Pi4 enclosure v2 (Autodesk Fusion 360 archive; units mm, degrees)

design "Pi4 enclosure" references "40x40x10 DC Fan"
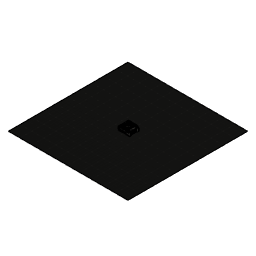
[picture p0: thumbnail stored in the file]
description: arrangementsContainer
named bodies: "Pi4_mount (1)", "LEFT", "RIGHT", "CENTRE"

design "40x40x10 DC Fan"
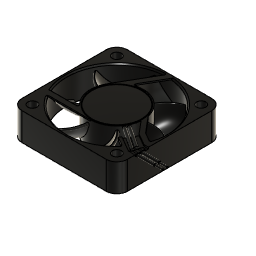
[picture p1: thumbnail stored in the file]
